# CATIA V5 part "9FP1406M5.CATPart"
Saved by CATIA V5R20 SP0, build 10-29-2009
Part number: 9FP1406M5
Revision: ANY
Definition: UNKNOWN
Nomenclature: 9FP1406M5
Source: Unknown
Bounding box of the stored display mesh (mm): x -6.727 to 6.727, y 0 to 6, z -6.9 to 6.9
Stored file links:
  C:\Users\Utente\Desktop\IO LAVORO\3D X SITO CF\CUMSA\3D files PW\pw080825\pw080825_ejection\9FP1406M5.CATPart
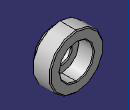
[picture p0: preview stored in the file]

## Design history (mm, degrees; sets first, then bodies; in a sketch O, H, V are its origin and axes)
Body1 "Chaflán1" (main body)
  Solid1: solid without history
